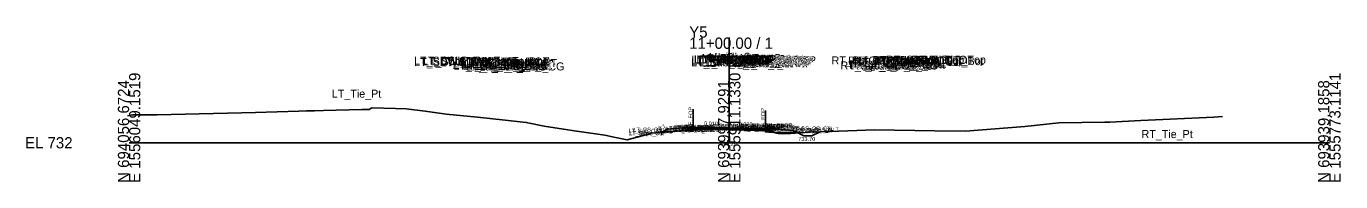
# Model space of a CAD drawing. Extents: x -26 to 4229, y -10 to 9523.
# Drawn here: x -25.7 to 302.8, y 1490.3 to 1529 of the extents above; entities that cross this region are included whole.
import ezdxf

# ---------------------------------------------------------------- set-up
doc = ezdxf.new("R2010")
doc.units = 0
for name, color, linetype in [('Default', 7, 'Continuous'), ('Exist CMT Pavement', 7, 'Continuous'), ('Exist Cross Section Cell', 7, 'Continuous'), ('Exist XS Center Line Elevation Label', 7, 'Continuous'), ('Exist XS Ground Line', 7, 'Continuous'), ('Prop CMT Pvmt Course 1', 7, 'Continuous'), ('Prop CMT Pvmt Course 1 Wedge', 7, 'Continuous'), ('Prop CMT Pvmt Course 2', 7, 'Continuous'), ('Prop CMT Pvmt Course 2 Wedge', 7, 'Continuous'), ('Prop CMT Pvmt Course 3', 7, 'Continuous'), ('Prop CMT Pvmt Course 3 Wedge', 7, 'Continuous'), ('Prop CMT Pvmt Surface', 7, 'Continuous'), ('Prop CMT Pvmt Surface Shoulder', 7, 'Continuous'), ('Prop CMT Pvmt Wedge Surface 1', 7, 'Continuous'), ('Prop CMT Pvmt Wedge Surface 2', 7, 'Continuous'), ('Prop CMT Pvmt Wedge Surface 3', 7, 'Continuous'), ('Prop CMT Shld Paved Course 1', 7, 'Continuous'), ('Prop CMT Shld Paved Course 2', 7, 'Continuous'), ('Prop CMT Shld Paved Course 3', 7, 'Continuous'), ('Prop CMT Slope Grass', 7, 'Continuous'), ('Prop CMT Subgrade Earthwork', 7, 'Continuous'), ('Prop XS Earthwork Shape', 7, 'Continuous'), ('Prop XS Label Text', 7, 'Continuous'), ('Prop XSC Text', 7, 'Continuous'), ('Scratch_Level_1', 7, 'Continuous')]:
    doc.layers.add(name, color=color, linetype=linetype)

msp = doc.modelspace()

# ---------------------------------------------------------------- linework, layer by layer
at = {"layer": 'Exist CMT Pavement'}
for p, q in [((142.59, 1503.32), (140.97, 1503.34)), ((140.97, 1503.34), (140.97, 1503.34)), ((157.43, 1503.06), (159.05, 1503.01))]:
    msp.add_line(p, q, dxfattribs=at)
for points in [[(142.59, 1503.32), (150, 1503.26)], [(150, 1503.26), (150.43, 1503.26), (150.92, 1503.25), (157.43, 1503.06)]]:
    msp.add_lwpolyline(points, dxfattribs=at)
at = {"layer": 'Exist Cross Section Cell'}
for p, q in [((150, 1500), (150, 1526.22)), ((0, 1500), (150, 1500)), ((150, 1500), (300, 1500))]:
    msp.add_line(p, q, dxfattribs=at)
at = {"layer": 'Exist XS Ground Line'}
msp.add_lwpolyline([(0, 1506.91), (0.83, 1506.92), (7.06, 1506.95), (31.61, 1507.58), (42.44, 1507.87), (44.32, 1507.92), (46.36, 1507.97), (48.58, 1508.02), (58.17, 1508.26), (59.06, 1508.27), (59.97, 1508.27), (60.28, 1508.48), (60.69, 1508.74), (66.56, 1508.53), (69.26, 1508.42), (73.99, 1507.89), (79.29, 1507.15), (87.06, 1506.38), (94.03, 1505.64), (99.27, 1505.09), (103.75, 1504.11), (110.78, 1503.06), (118.93, 1501.88), (121.58, 1501.32), (124.51, 1500.75), (128.54, 1501.8), (130.53, 1502.37), (137.06, 1502.91), (139.56, 1503.2), (140.97, 1503.34), (141.4, 1503.33), (150, 1503.26), (150.43, 1503.26), (150.92, 1503.25), (159.05, 1503.01), (162.27, 1502.34), (163.42, 1502.25), (165.35, 1502.34), (167.66, 1502.5), (170.21, 1502.63), (172.97, 1502.76), (186.32, 1503.22), (201.36, 1503.01), (209.05, 1502.9), (223.85, 1504.08), (232.41, 1504.93), (243.87, 1505.14), (245.15, 1505.16), (252.87, 1505.53), (271.12, 1506.41), (273.27, 1506.52)], dxfattribs=at)
at = {"layer": 'Prop CMT Pvmt Course 1'}
for points in [[(150, 1503.76), (140.59, 1503.85)], [(140.59, 1503.85), (140.59, 1503.6)], [(140.59, 1503.6), (140.97, 1503.6)], [(140.97, 1503.6), (140.97, 1503.72)], [(140.97, 1503.72), (150, 1503.63)], [(150, 1503.51), (150, 1503.76)], [(150, 1503.76), (159.91, 1503.56)], [(150, 1503.51), (150, 1503.76)], [(150, 1503.63), (150, 1503.51), (150, 1503.51)], [(157.43, 1503.48), (150, 1503.63)], [(150, 1503.63), (150, 1503.51), (150, 1503.51)], [(159.05, 1503.33), (159.05, 1503.45)], [(159.91, 1503.31), (159.05, 1503.33)], [(159.91, 1503.56), (159.91, 1503.31)]]:
    msp.add_lwpolyline(points, dxfattribs=at)
at = {"layer": 'Prop CMT Pvmt Course 1 Wedge'}
for points in [[(140.97, 1503.6), (140.97, 1503.72)], [(142.59, 1503.71), (150, 1503.63)], [(150, 1503.51), (142.59, 1503.58)], [(150, 1503.63), (150, 1503.51)], [(150, 1503.51), (150, 1503.63)], [(150, 1503.63), (159.05, 1503.45)], [(157.43, 1503.36), (150, 1503.51)], [(159.05, 1503.45), (159.05, 1503.33)]]:
    msp.add_lwpolyline(points, dxfattribs=at)
at = {"layer": 'Prop CMT Pvmt Course 2'}
for points in [[(142.59, 1503.58), (140.59, 1503.6)], [(140.59, 1503.6), (140.59, 1503.35)], [(140.59, 1503.35), (140.97, 1503.35)], [(140.97, 1503.35), (140.97, 1503.6)], [(157.43, 1503.36), (159.91, 1503.31)], [(159.05, 1503.08), (159.05, 1503.33)], [(159.91, 1503.06), (159.05, 1503.08)], [(159.91, 1503.31), (159.91, 1503.06)]]:
    msp.add_lwpolyline(points, dxfattribs=at)
at = {"layer": 'Prop CMT Pvmt Course 2 Wedge'}
for points in [[(140.97, 1503.56), (140.97, 1503.6)], [(142.59, 1503.58), (150, 1503.51)], [(150, 1503.26), (142.59, 1503.32)], [(150, 1503.51), (150, 1503.26)], [(150, 1503.26), (150, 1503.51)], [(150, 1503.51), (157.43, 1503.36)], [(159.05, 1503.33), (159.05, 1503.08)]]:
    msp.add_lwpolyline(points, dxfattribs=at)
at = {"layer": 'Prop CMT Pvmt Course 3'}
for points in [[(140.97, 1503.35), (140.59, 1503.35)], [(140.59, 1503.35), (140.59, 1502.98)], [(140.59, 1502.98), (140.97, 1502.97)], [(140.97, 1502.97), (140.97, 1503.35)], [(159.05, 1503.08), (159.91, 1503.06)], [(159.05, 1502.7), (159.05, 1503.08)], [(159.91, 1502.68), (159.05, 1502.7)], [(159.91, 1503.06), (159.91, 1502.68)]]:
    msp.add_lwpolyline(points, dxfattribs=at)
at = {"layer": 'Prop CMT Pvmt Course 3 Wedge'}
msp.add_line((142.59, 1503.33), (147.07, 1503.29), dxfattribs=at)
for points in [[(157.43, 1503.06), (150.92, 1503.25), (150.43, 1503.26), (150.28, 1503.26)], [(150.28, 1503.26), (150.43, 1503.26)], [(151.89, 1503.22), (159.05, 1503.08)], [(159.05, 1503.08), (159.05, 1502.7)]]:
    msp.add_lwpolyline(points, dxfattribs=at)
at = {"layer": 'Prop CMT Pvmt Surface'}
for points in [[(150, 1503.76), (140.59, 1503.85)], [(150, 1503.76), (159.91, 1503.56)]]:
    msp.add_lwpolyline(points, dxfattribs=at)
at = {"layer": 'Prop CMT Pvmt Surface Shoulder'}
for points in [[(140.59, 1503.85), (140.59, 1503.85)], [(159.91, 1503.56), (159.91, 1503.56)]]:
    msp.add_lwpolyline(points, dxfattribs=at)
at = {"layer": 'Prop CMT Pvmt Wedge Surface 1'}
for points in [[(140.59, 1503.6), (140.59, 1503.85)], [(140.97, 1503.6), (140.59, 1503.6)], [(140.97, 1503.72), (140.97, 1503.6)], [(150, 1503.63), (142.59, 1503.71)], [(150, 1503.63), (157.43, 1503.48)], [(159.05, 1503.45), (159.05, 1503.33)], [(159.05, 1503.33), (159.91, 1503.31)], [(159.91, 1503.31), (159.91, 1503.56)]]:
    msp.add_lwpolyline(points, dxfattribs=at)
at = {"layer": 'Prop CMT Pvmt Wedge Surface 2'}
for points in [[(140.59, 1503.6), (140.59, 1503.85)], [(150, 1503.51), (140.59, 1503.6)], [(150, 1503.51), (159.91, 1503.31)], [(159.91, 1503.31), (159.91, 1503.56)]]:
    msp.add_lwpolyline(points, dxfattribs=at)
at = {"layer": 'Prop CMT Pvmt Wedge Surface 3'}
for points in [[(140.59, 1503.35), (140.59, 1503.85)], [(150, 1503.26), (140.59, 1503.35)], [(150, 1503.26), (159.91, 1503.06)], [(159.91, 1503.06), (159.91, 1503.56)]]:
    msp.add_lwpolyline(points, dxfattribs=at)
at = {"layer": 'Prop CMT Shld Paved Course 1'}
for points in [[(140.59, 1503.85), (140.34, 1503.6)], [(140.34, 1503.6), (140.59, 1503.6)], [(140.59, 1503.85), (140.59, 1503.85)], [(140.59, 1503.6), (140.59, 1503.85)], [(159.91, 1503.56), (159.91, 1503.56)], [(159.91, 1503.56), (160.16, 1503.3)], [(159.91, 1503.31), (159.91, 1503.56)], [(160.16, 1503.3), (159.91, 1503.31)]]:
    msp.add_lwpolyline(points, dxfattribs=at)
at = {"layer": 'Prop CMT Shld Paved Course 2'}
for points in [[(140.59, 1503.6), (140.34, 1503.6), (140.08, 1503.34)], [(140.08, 1503.34), (140.59, 1503.35)], [(140.59, 1503.35), (140.59, 1503.6)], [(159.91, 1503.31), (160.16, 1503.3), (160.42, 1503.05)], [(159.91, 1503.06), (159.91, 1503.31)], [(160.42, 1503.05), (159.91, 1503.06)]]:
    msp.add_lwpolyline(points, dxfattribs=at)
at = {"layer": 'Prop CMT Shld Paved Course 3'}
for points in [[(140.59, 1503.35), (140.08, 1503.34), (139.58, 1503.33), (139.2, 1502.95)], [(139.2, 1502.95), (140.59, 1502.98)], [(140.59, 1502.98), (140.59, 1503.35)], [(159.91, 1503.06), (160.42, 1503.05), (160.92, 1503.04), (161.3, 1502.66)], [(159.91, 1502.68), (159.91, 1503.06)], [(161.3, 1502.66), (159.91, 1502.68)]]:
    msp.add_lwpolyline(points, dxfattribs=at)
at = {"layer": 'Prop CMT Slope Grass'}
for p, q in [((165.91, 1503.08), (168.65, 1501.7)), ((168.65, 1501.7), (170.65, 1501.7)), ((172.74, 1502.74), (170.65, 1501.7))]:
    msp.add_line(p, q, dxfattribs=at)
for points in [[(140.59, 1503.85), (134.59, 1503.37), (132.99, 1502.57)], [(159.91, 1503.56), (165.91, 1503.08)]]:
    msp.add_lwpolyline(points, dxfattribs=at)
at = {"layer": 'Prop CMT Subgrade Earthwork'}
for points in [[(139.2, 1502.95), (133.52, 1502.83)], [(140.59, 1502.98), (139.2, 1502.95)], [(140.97, 1502.97), (140.59, 1502.98)], [(140.97, 1502.97), (140.97, 1503.34)], [(159.05, 1502.7), (159.05, 1503.01)], [(159.05, 1502.7), (159.91, 1502.68)], [(159.91, 1502.68), (161.3, 1502.66)], [(166.98, 1502.54), (161.3, 1502.66)]]:
    msp.add_lwpolyline(points, dxfattribs=at)
at = {"layer": 'Prop XS Earthwork Shape'}
for points in [[(132.99, 1502.57), (136.94, 1502.9), (133.52, 1502.83)], [(140.97, 1502.97), (140.59, 1502.98), (139.2, 1502.95), (136.94, 1502.9), (137.06, 1502.91), (139.56, 1503.2), (140.97, 1503.34)], [(140.97, 1503.34), (141.4, 1503.33), (142.59, 1503.32)], [(159.91, 1502.68), (160.7, 1502.67), (159.05, 1503.01), (159.05, 1502.7)], [(166.98, 1502.54), (167.14, 1502.46), (165.35, 1502.34), (163.42, 1502.25), (162.27, 1502.34), (160.7, 1502.67), (161.3, 1502.66)], [(172.74, 1502.74), (170.65, 1501.7), (168.65, 1501.7), (167.14, 1502.46), (167.66, 1502.5), (170.21, 1502.63)]]:
    msp.add_lwpolyline(points, close=True, dxfattribs=at)
at = {"layer": 'Prop XS Label Text'}
for p, q in [((140.97, 1508.34), (140.97, 1503.34)), ((159.05, 1508.01), (159.05, 1503.01))]:
    msp.add_line(p, q, dxfattribs=at)

# ---------------------------------------------------------------- texts
at = {"layer": 'Default'}
for s, height, p in [('LT_SDWK_Out_Top', 2, (71.24, 1519.46)), ('LT_SDWK_Out_Bot', 2, (71.27, 1519.12)), ('LT_CSLP_Pnt', 2, (73.17, 1519.48)), ('LT_Sub_Trench_Out_DLT', 2, (73.49, 1519.28)), ('LT_SDWK_In_Top', 2, (77.86, 1519.36)), ('LT_CG_Top_Face', 2, (82.76, 1519.24)), ('LT_CG_Top_BOC', 2, (83.28, 1519.24)), ('LT_Sub_OEEOP', 2, (140.46, 1519.06)), ('LT_PV2_OEEOP', 2, (140.56, 1519.69)), ('LT_PV3_OEEOP', 2, (140.56, 1519.44)), ('LT_PV1_OEEOP', 2, (141.12, 1519.81)), ('LT_PV2_IEEOP', 2, (141.2, 1519.69)), ('LT_PV1_IEEOP', 2, (141.77, 1519.81)), ('LT_PV2_PGL1', 2, (142.13, 1519.69)), ('LT_PV3_PGL1', 2, (142.13, 1519.44)), ('LT_PV2_PGL', 2, (142.46, 1519.69)), ('LT_PV1_PGL', 2, (143.03, 1519.94)), ('MI_Face In', 2, (143.15, 1520.1)), ('MI_Bot In', 2, (144.13, 1519.94)), ('MI_Top In', 2, (144.86, 1520.35)), ('MI_Crown', 2, (149.07, 1520.43)), ('RT_PV2_OEEOP', 2, (150.01, 1519.45)), ('RT_PV3_OEEOP', 2, (150.01, 1519.2)), ('RT_PV1_OEEOP', 2, (150.58, 1519.57)), ('RT_PV2_IEEOP', 2, (150.66, 1519.45)), ('MI_Face Out', 2, (151.01, 1519.86)), ('MI_Top Out', 2, (151.22, 1520.11)), ('RT_PV1_IEEOP', 2, (151.22, 1519.57)), ('RT_PV2_PGL1', 2, (151.58, 1519.45)), ('RT_PV3_PGL1', 2, (151.58, 1519.2)), ('RT_PV2_PGL', 2, (151.92, 1519.45)), ('MI_Bot Out', 2, (152.01, 1519.7)), ('RT_PV1_PGL', 2, (152.48, 1519.7)), ('RT_Sub_Trench_Out_DLT', 2, (175.59, 1519.52)), ('RT_CG_Top_Face', 2, (179.71, 1519.48)), ('RT_PV1_OEOT', 2, (181.19, 1519.1)), ('RT_CG_Top_BOC', 2, (181.24, 1519.48)), ('RT_SDWK_In_Top', 2, (185.81, 1519.6)), ('RT_SDWK_In_Bot', 2, (185.84, 1519.26)), ('RT_SDWK_Out_Top', 2, (189.19, 1519.7)), ('RT_SDWK_Out_Bot', 2, (189.22, 1519.36)), ('RT_Shld_O', 2, (195.54, 1519.68)), ('CSLP_Pnt', 2, (197.87, 1519.72)), ('LT_SDWK_In_Bot', 2, (77.89, 1519.02)), ('LT_CG1_Shelf_Out', 2, (81.05, 1518.22)), ('LT_CG_Bot_BOC', 2, (83.31, 1518.23)), ('LT_CG_Top_Gut', 2, (83.74, 1518.74)), ('LT_Sub_OEOP', 2, (84.36, 1517.96)), ('LT_Sub_OEOT_CG', 2, (84.87, 1518.03)), ('LT_CG_Bot_IE', 2, (87.41, 1518.28)), ('LT_Sub_OEOT', 2, (87.58, 1517.99)), ('LT_PV2_OEOT', 2, (87.67, 1518.61)), ('LT_PV3_OEOT', 2, (87.67, 1518.36)), ('LT_PV1_OEOT', 2, (88.24, 1518.86)), ('LT_PV4_PGL', 2, (142.46, 1519.06)), ('RT_Sub_OEEOP', 2, (149.92, 1518.82)), ('RT_PV4_PGL', 2, (151.92, 1518.82)), ('RT_Sub_OEOT_CG', 2, (177.82, 1518.27)), ('RT_CG1_Shelf_Out', 2, (180, 1518.46)), ('RT_CG_Bot_IE', 2, (180.37, 1518.52)), ('RT_Sub_OEOT', 2, (180.53, 1518.23)), ('RT_PV2_OEOT', 2, (180.63, 1518.85)), ('RT_PV3_OEOT', 2, (180.63, 1518.6)), ('RT_CG_Top_Gut', 2, (180.69, 1518.98)), ('RT_CG_Bot_BOC', 2, (181.27, 1518.47)), ('RT_Sub_OEOP', 2, (183.82, 1518.2)), ('LT_Tie_Pt', 2, (50.69, 1511.23)), ('RT_Tie_Pt', 2, (253.07, 1501.17)), ('-', 0.0001, (0, 1500)), ('-', 0.0001, (0, 1500)), ('-', 0.0001, (0, 1500)), ('-', 0.0001, (0, 1500)), ('-', 0.0001, (0, 1500)), ('-', 0.0001, (0, 1500)), ('-', 0.0001, (0, 1500)), ('-', 0.0001, (0, 1500)), ('-', 0.0001, (0, 1500)), ('-', 0.0001, (0, 1500))]:
    msp.add_text(s, height=height, dxfattribs=at).set_placement(p)
at = {"layer": 'Exist Cross Section Cell'}
for s, p in [('Y5', (140, 1526.22)), ('11+00.00 / 1', (140, 1523.42)), ('EL 732', (-26, 1498.6))]:
    msp.add_text(s, height=2.8, dxfattribs=at).set_placement(p)
for s, p in [('N 694056.6724', (0, 1490)), ('E 1556049.1519', (2.8, 1490)), ('N 693997.9291', (150, 1490)), ('E 1555911.1330', (152.8, 1490)), ('N 693939.1858', (300, 1490)), ('E 1555773.1141', (302.8, 1490))]:
    msp.add_text(s, height=2.8, rotation=90, dxfattribs=at).set_placement(p)
at = {"layer": 'Exist XS Center Line Elevation Label'}
msp.add_text('735.26', height=1, dxfattribs=at).set_placement((147.73, 1499.26))
at = {"layer": 'Prop XS Label Text'}
for p in [(140.87, 1504.35), (158.95, 1504.03)]:
    msp.add_text('E. EOP', height=1, rotation=90, dxfattribs=at).set_placement(p)
at = {"layer": 'Prop XSC Text'}
for s, rotation, p in [('0.010', 359.4271, (143.71, 1504.31)), ('0.020', 358.8542, (152.37, 1504.16)), ('2:1', 26.5651, (132.53, 1502.99)), ('2:1', 333.4349, (166.67, 1503.06)), ('2:1', 26.5651, (170.74, 1502.25))]:
    msp.add_text(s, height=1, rotation=rotation, dxfattribs=at).set_placement(p)
msp.add_text('733.70', height=1, dxfattribs=at).set_placement((167.27, 1500.45))
at = {"layer": 'Scratch_Level_1'}
for s, p in [('PV1_PGL', (147.47, 1503.76)), ('RT_PV1_OEEOP', (152.89, 1503.72)), ('RT_PV1_OEOT', (155.71, 1503.87)), ('RT_PS1_OEOP', (155.75, 1503.87)), ('LT_Slope_Cut', (124.82, 1501.89)), ('LT_Sub_OSS_DLT', (124.86, 1502.49)), ('LT_Slope_Fill', (125.05, 1501.89)), ('LT_GS_OS_CTL', (126.05, 1502.78)), ('LT_Sub_Trench_Out', (133.31, 1502.68)), ('LT_PS3_Shelf_Out', (134.24, 1503.06)), ('LT_PS3_OEOP', (135.87, 1503.07)), ('LT_PS2_OEOP', (136.12, 1503.32)), ('LT_PV2_OEOT', (136.34, 1503.33)), ('LT_PV3_OEOT', (136.34, 1503.08)), ('LT_Sub_OEOT', (136.36, 1502.7)), ('LT_PV1_OEOT', (136.46, 1503.58)), ('LT_PS1_OEOP', (136.5, 1503.58)), ('LT_PV_OEEOP_EG', (137.19, 1503.34)), ('LT_Sub Tie Out', (137.75, 1503.33)), ('LT_PV2_OEEOP', (137.98, 1503.37)), ('LT_PV3_OEEOP', (137.98, 1503.12)), ('LT_Sub_OEEOP', (138.01, 1502.74)), ('LT_PV1_OEEOP', (138.1, 1503.49)), ('RT_PV_IEEOP_EG', (144.92, 1503.27)), ('LT_PV_IEEOP_EG', (144.98, 1503.27)), ('RT_PV2_IEEOP', (145.71, 1503.52)), ('RT_PV3_IEEOP', (145.71, 1503.27)), ('LT_PV2_IEEOP', (145.77, 1503.52)), ('LT_PV3_IEEOP', (145.77, 1503.27)), ('RT_PV1_IEEOP', (145.83, 1503.64)), ('LT_PV1_IEEOP', (145.89, 1503.64)), ('PV2_PGL', (147.35, 1503.51)), ('RT_PV_OEEOP_EG', (151.97, 1503.07)), ('RT_Sub Tie Out', (152.53, 1503.07)), ('RT_PV2_OEEOP', (152.77, 1503.59)), ('RT_PV3_OEEOP', (152.77, 1503.34)), ('RT_Sub_OEEOP', (152.79, 1502.97)), ('RT_Sub_Trench_Out', (155.35, 1502.97)), ('RT_PS3_Shelf_Out', (155.51, 1503.35)), ('RT_PV2_OEOT', (155.59, 1503.62)), ('RT_PV3_OEOT', (155.59, 1503.37)), ('RT_Sub_OEOT', (155.62, 1502.99)), ('RT_PS2_OEOP', (155.89, 1503.61)), ('RT_PS3_OEOP', (156.14, 1503.36)), ('RT_Sub_OSS_DLT', (165.27, 1502.78)), ('RT_GS_OS_CTL', (165.31, 1503.07)), ('RT_Slope_Cut', (166.66, 1502.66)), ('RT_Slope_Fill', (166.9, 1502.66))]:
    msp.add_text(s, height=1, rotation=359.8763, dxfattribs=at).set_placement(p)

doc.saveas('drawing.dxf')
